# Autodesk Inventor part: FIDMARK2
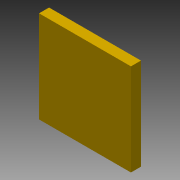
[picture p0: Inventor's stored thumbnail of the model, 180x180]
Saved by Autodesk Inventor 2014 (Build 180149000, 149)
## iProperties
Shininess: 64.0
Length Units: 11272
Angle Units: 11279
Time Units: 11290
Mass Units: 11286
Length Display Precision: 3
Angle Display Precision: 2
Compacted: True
Part Number: FIDMARK2
Document SubType Name: Modeling
Created: 2003-04
Designer: t_enrig
Manufacturer: Standard
Standards Organization: Custom
Density: 1 g/cm^3
Mass: 0.0023794 g
Surface Area: 0.190193 cm^2
Volume: 0.0023794 cm^3
Material: Generic
Appearance: TranslatedColorStyle
Density: 0.0
Volumn: 0.0
Area: 0.0
PropertySet Name: Model Information
Control State: 0
Master: False
Checked Out: False
Author: t_enrig
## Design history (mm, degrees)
feature "Base1"
body "Solid1"
